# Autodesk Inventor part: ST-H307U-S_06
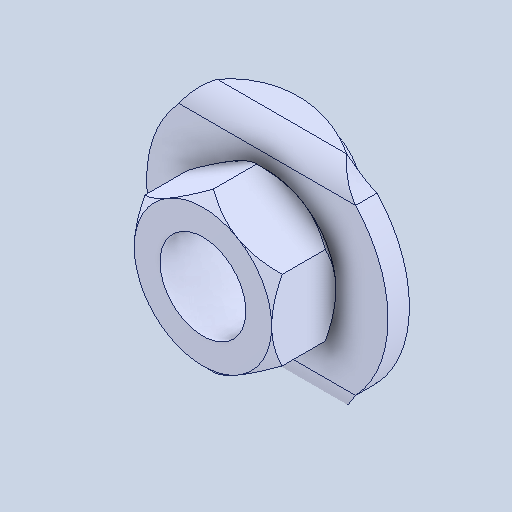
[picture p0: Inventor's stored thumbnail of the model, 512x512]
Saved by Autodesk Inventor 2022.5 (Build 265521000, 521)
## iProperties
Created: 2024-07
Part Number: ST-H307U-S_06
Material: 一般
Document SubType Name: Modeling
Designer: ImaoCorp
Density: 1 g/cm^3
Appearance: 既定
Author: ImaoCorp
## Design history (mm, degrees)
feature "ST-H307U-S_06"
node "ソリッド1"
